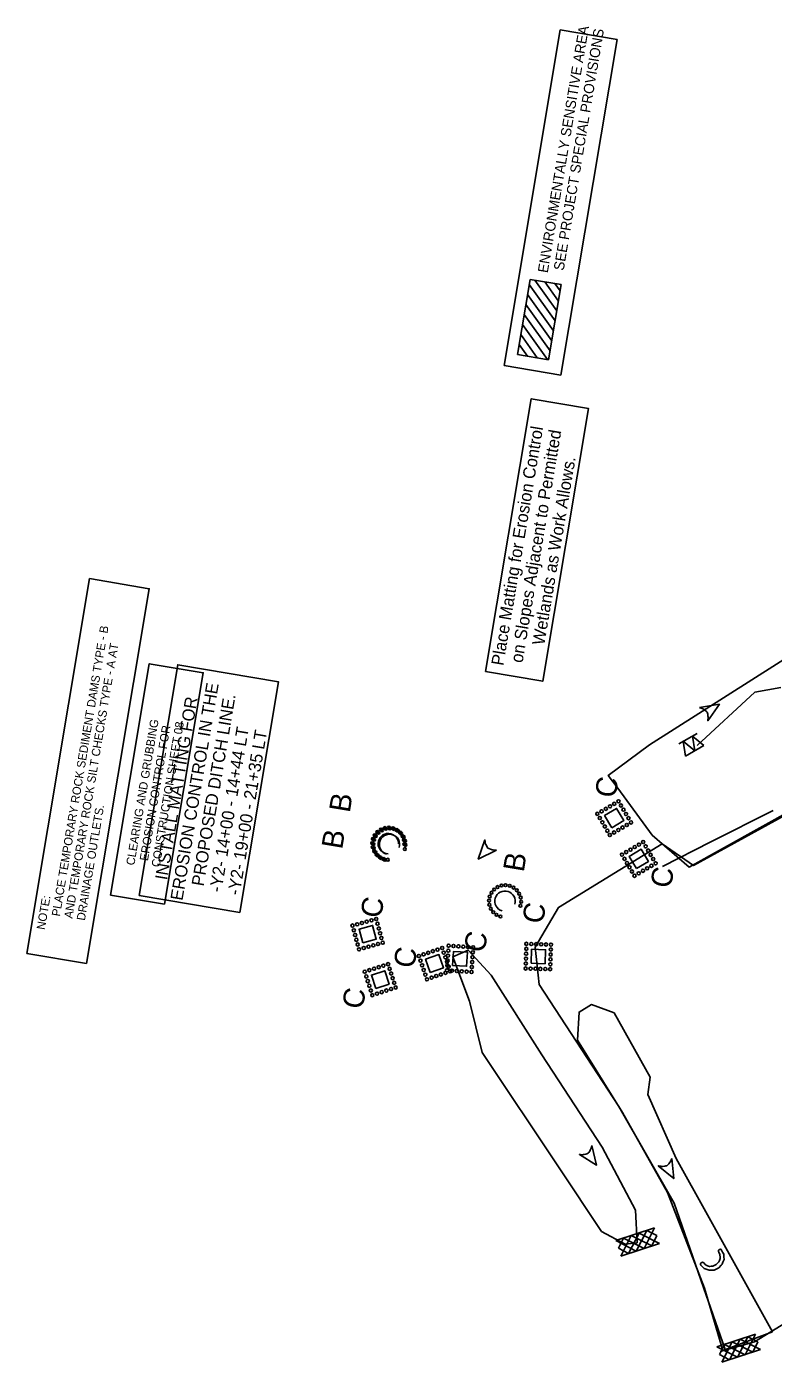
# Model space of a CAD drawing. Extents: x 2470000 to 2520000, y 340000 to 380000.
# Drawn here: x 2482102 to 2482633, y 367159 to 368109 of the extents above; entities that cross this region are included whole.
import ezdxf

# ---------------------------------------------------------------- set-up
doc = ezdxf.new("R2010")
doc.units = 0
for name, color, linetype in [('Bare Soil (Coastal) Drainage Area Border FG Drainage', 7, 'Continuous'), ('Construction Sheet Number Note CG CELL', 7, 'Continuous'), ('Environmentally Sensitive Area Note CG CELL', 7, 'Continuous'), ('Label B CG CELL', 7, 'Continuous'), ('Label B Final CELL', 7, 'Continuous'), ('Matting in Proposed Ditchline Note Final CELL', 7, 'Continuous'), ('Matting on Slope at Wetlands Note Final CELL', 7, 'Continuous'), ('Prop Guardrail', 7, 'Continuous'), ('Rock Pipe Inlet Sediment Trap Type B CG CELL', 7, 'Continuous'), ('Rock Pipe Inlet Sediment Trap Type B Final CELL', 7, 'Continuous'), ('Rock Silt Check Type A Both CELL', 7, 'Continuous'), ('Rock Silt Check Type B CG CELL', 7, 'Continuous'), ('Scratch_Level_5', 7, 'Continuous'), ('Sediment Dams and Silt Check Note CG CELL', 7, 'Continuous'), ('Special Sediment Control Fence Section Final CELL', 7, 'Continuous'), ('Temporary Silt Fence Final', 7, 'Continuous'), ('Wattle Both CELL', 7, 'Continuous')]:
    doc.layers.add(name, color=color, linetype=linetype)

# ---------------------------------------------------------------- blocks, each defined once
blk = doc.blocks.new('C3')
at = {"layer": 'Prop Guardrail'}
blk.add_text('C', height=0.3, dxfattribs=at).set_placement((-0.161, -0.136))
blk = doc.blocks.new('CGNT2')
at = {"layer": 'Sediment Dams and Silt Check Note CG CELL'}
blk.add_lwpolyline([(-2.704, 0.431), (2.704, 0.43125), (2.704, -0.43), (-2.704, -0.43)], close=True, dxfattribs=at)
for s, p in [('NOTE:', (-2.335, 0.231)), ('     PLACE TEMPORARY ROCK SEDIMENT DAMS TYPE - B', (-2.335, 0.05125)), ('     AND TEMPORARY ROCK SILT CHECKS TYPE - A AT', (-2.335, -0.129)), ('     DRAINAGE OUTLETS.', (-2.335, -0.309))]:
    blk.add_text(s, height=0.12, dxfattribs=at).set_placement(p)
blk = doc.blocks.new('B1')
at = {"layer": 'Label B CG CELL'}
blk.add_text('B', height=0.3, dxfattribs=at).set_placement((-0.106, -0.151))
blk = doc.blocks.new('B3')
at = {"layer": 'Label B Final CELL'}
blk.add_text('B', height=0.3, dxfattribs=at).set_placement((-0.106, -0.151))
blk = doc.blocks.new('MATSLOPEWET')
at = {"layer": 'Matting on Slope at Wetlands Note Final CELL'}
blk.add_lwpolyline([(-1.851, 0.435), (2.086, 0.435), (2.086, -0.39), (-1.851, -0.39)], close=True, dxfattribs=at)
for s, p in [('Place Matting for Erosion Control', (-1.733, 0.199)), ('on Slopes Adjacent to Permitted', (-1.649, -0.064)), ('Wetlands as Work Allows. ', (-1.349, -0.328))]:
    blk.add_text(s, height=0.17569, dxfattribs=at).set_placement(p)

msp = doc.modelspace()

# ---------------------------------------------------------------- linework, layer by layer
at = {"layer": 'Bare Soil (Coastal) Drainage Area Border FG Drainage'}
for points in [[(2482695.58, 367580.14), (2482733.84, 367608.85), (2482716.34, 367636.65), (2482690.63, 367690.71), (2482545.08, 367598.01), (2482515.7, 367576.31), (2482522.38, 367567.27), (2482547.02, 367533.91), (2482573.34, 367511.14), (2482699.03, 367581.01)], [(2482595.21, 367166.32), (2482619.75, 367173.34), (2482682.86, 367212.09), (2482758.96, 367340.68), (2482702.55, 367547.73), (2482665.92, 367561.27), (2482576.36, 367512.28), (2482554.09, 367527.55), (2482480.29, 367482.43), (2482463.55, 367454.21), (2482466.48, 367427.48), (2482523.08, 367340.84), (2482562.66, 367271.9), (2482583.45, 367212.07), (2482598.79, 367167.93)], [(2482536.25, 367243.82), (2482535.06, 367267.03), (2482511.35, 367311.91), (2482468.3, 367377.44), (2482432.22, 367434.11), (2482416.01, 367452.1), (2482404.98, 367447.31), (2482416.78, 367415.69), (2482425.94, 367379.17), (2482480.67, 367297.21), (2482510.95, 367251.86), (2482527.74, 367242.92)], [(2482597.34, 367167.09), (2482632.58, 367180.48), (2482586.27, 367263.61), (2482563.96, 367303.65), (2482543.72, 367349.35), (2482545.43, 367361.63), (2482519.8, 367407.5), (2482503.66, 367413.25), (2482494.87, 367407.92), (2482493.76, 367387.92), (2482525.87, 367336.43), (2482557.85, 367279.61), (2482584.15, 367211.48)]]:
    msp.add_lwpolyline(points, close=True, dxfattribs=at)
at = {"layer": 'Construction Sheet Number Note CG CELL'}
msp.add_lwpolyline([(2482161.23, 367491.21), (2482188.83, 367655.82), (2482227.3, 367649.37), (2482199.71, 367484.77)], close=True, dxfattribs=at)
at = {"layer": 'Environmentally Sensitive Area Note CG CELL'}
for p, q in [((2482441.48, 367867.98), (2482481.53, 368106.86)), ((2482481.53, 368106.86), (2482521.96, 368100.08)), ((2482521.96, 368100.08), (2482481.95, 367861.19)), ((2482451.02, 367875.81), (2482459.99, 367929.32)), ((2482477.83, 367899.68), (2482459.36, 367925.55)), ((2482459.99, 367929.32), (2482482.18, 367925.59)), ((2482479.02, 367906.8), (2482463.38, 367928.74)), ((2482480.22, 367913.9), (2482470.53, 367927.55)), ((2482482.18, 367925.59), (2482473.21, 367872.09)), ((2482481.41, 367921.03), (2482477.64, 367926.35)), ((2482476.64, 367892.57), (2482458.17, 367918.44)), ((2482475.45, 367885.45), (2482456.98, 367911.33)), ((2482472.3, 367872.25), (2482454.59, 367897.09)), ((2482474.25, 367878.34), (2482455.78, 367904.21)), ((2482465.15, 367873.44), (2482453.4, 367889.98)), ((2482458.04, 367874.64), (2482452.2, 367882.86)), ((2482481.95, 367861.19), (2482441.48, 367867.98)), ((2482473.21, 367872.09), (2482451.02, 367875.81))]:
    msp.add_line(p, q, dxfattribs=at)
at = {"layer": 'Matting in Proposed Ditchline Note Final CELL'}
msp.add_lwpolyline([(2482181.65, 367490.9), (2482209.16, 367655.03), (2482280.79, 367643.02), (2482253.29, 367478.89)], close=True, dxfattribs=at)
at = {"layer": 'Rock Pipe Inlet Sediment Trap Type B CG CELL'}
for centre in [(2482349.38, 367533.82), (2482351.27, 367536.13), (2482353.69, 367537.87), (2482356.48, 367538.92), (2482359.45, 367539.22), (2482362.39, 367538.73), (2482365.11, 367537.5), (2482367.42, 367535.61), (2482347.67, 367528.16), (2482347.96, 367525.19), (2482348.15, 367531.1), (2482369.16, 367533.19), (2482370.21, 367530.4), (2482370.5, 367527.43), (2482349.02, 367522.4), (2482350.76, 367519.98), (2482353.06, 367518.09), (2482355.78, 367516.86), (2482358.72, 367516.38), (2482436.81, 367496.92), (2482439.61, 367497.96), (2482442.57, 367498.25), (2482445.52, 367497.76), (2482448.23, 367496.52), (2482430.76, 367487.23), (2482431.25, 367490.17), (2482432.49, 367492.89), (2482434.38, 367495.19), (2482450.53, 367494.62), (2482452.26, 367492.19), (2482453.31, 367489.4), (2482453.59, 367486.43), (2482431.04, 367484.26), (2482432.09, 367481.47), (2482433.82, 367479.04), (2482436.12, 367477.14), (2482453.1, 367483.49), (2482438.84, 367475.91)]:
    msp.add_circle(centre, 1.01, dxfattribs=at)
for centre, start, end in [((2482359.09, 367527.8), 358.18137, 268.17255), ((2482442.18, 367486.83), 343.00443, 252.99561)]:
    msp.add_arc(centre, 7.26, start, end, dxfattribs=at)
at = {"layer": 'Rock Pipe Inlet Sediment Trap Type B Final CELL'}
for centre in [(2482352.05, 367535.51), (2482354.47, 367537.26), (2482357.25, 367538.32), (2482360.22, 367538.63), (2482363.16, 367538.15), (2482365.88, 367536.93), (2482368.2, 367535.05), (2482348.48, 367527.53), (2482348.78, 367524.56), (2482348.95, 367530.47), (2482350.17, 367533.19), (2482369.95, 367532.64), (2482370.84, 367523.94), (2482371.01, 367529.85), (2482371.32, 367526.88), (2482349.85, 367521.77), (2482351.59, 367519.36), (2482353.91, 367517.48), (2482356.63, 367516.26)]:
    msp.add_circle(centre, 1.01, dxfattribs=at)
msp.add_arc((2482359.9, 367527.21), 7.26, 343.3928, 253.38398, dxfattribs=at)
at = {"layer": 'Rock Silt Check Type A Both CELL'}
for p, q in [((2482521.05, 367245.33), (2482548.51, 367254.32)), ((2482537.54, 367250.72), (2482530.11, 367236.14)), ((2482543, 367252.53), (2482535.62, 367237.94)), ((2482552.11, 367243.34), (2482537.54, 367250.72)), ((2482548.51, 367254.32), (2482541.13, 367239.75)), ((2482550.31, 367248.86), (2482543, 367252.53)), ((2482535.62, 367237.94), (2482521.05, 367245.33)), ((2482526.48, 367247.05), (2482522.83, 367239.86)), ((2482530.11, 367236.14), (2482522.83, 367239.86)), ((2482532.02, 367248.92), (2482524.64, 367234.35)), ((2482524.64, 367234.35), (2482552.11, 367243.34)), ((2482541.13, 367239.75), (2482526.51, 367247.11)), ((2482546.6, 367241.54), (2482532.02, 367248.92)), ((2482550.31, 367248.86), (2482546.6, 367241.54)), ((2482592.98, 367169.73), (2482620.45, 367178.73)), ((2482603.96, 367173.33), (2482596.58, 367158.76)), ((2482609.47, 367175.13), (2482602.04, 367160.55)), ((2482618.53, 367165.95), (2482603.96, 367173.33)), ((2482614.93, 367176.93), (2482607.55, 367162.35)), ((2482624.04, 367167.75), (2482609.47, 367175.13)), ((2482620.45, 367178.73), (2482613.07, 367164.16)), ((2482622.25, 367173.27), (2482614.93, 367176.93)), ((2482622.25, 367173.27), (2482618.53, 367165.95)), ((2482607.55, 367162.35), (2482592.98, 367169.73)), ((2482598.42, 367171.46), (2482594.76, 367164.26)), ((2482602.04, 367160.55), (2482594.76, 367164.26)), ((2482596.58, 367158.76), (2482624.04, 367167.75)), ((2482613.07, 367164.16), (2482598.45, 367171.52))]:
    msp.add_line(p, q, dxfattribs=at)
at = {"layer": 'Rock Silt Check Type B CG CELL'}
for points in [[(2482580.6, 367624.55), (2482594.8, 367626.97), (2482586.46, 367615.24), (2482586.58, 367616.08), (2482586.71, 367617.1), (2482586.71, 367617.98), (2482586.66, 367618.6), (2482586.44, 367619.88), (2482586.24, 367620.66), (2482586.04, 367621.46), (2482585.43, 367622.05), (2482584.51, 367622.76), (2482583.9, 367623.19), (2482583.53, 367623.37), (2482583.08, 367623.63), (2482582.45, 367623.94), (2482581.86, 367624.15), (2482581.11, 367624.4)], [(2482436.04, 367523.2), (2482423.11, 367516.86), (2482427.78, 367530.47), (2482427.91, 367529.63), (2482428.07, 367528.62), (2482428.33, 367527.77), (2482428.55, 367527.19), (2482429.12, 367526.03), (2482429.53, 367525.34), (2482429.95, 367524.63), (2482430.7, 367524.23), (2482431.78, 367523.81), (2482432.49, 367523.58), (2482432.89, 367523.5), (2482433.41, 367523.39), (2482434.1, 367523.26), (2482434.72, 367523.23), (2482435.51, 367523.2)], [(2482503.96, 367313.08), (2482507.33, 367299.09), (2482495.06, 367306.61), (2482495.91, 367306.55), (2482496.93, 367306.48), (2482497.81, 367306.55), (2482498.42, 367306.64), (2482499.69, 367306.95), (2482500.45, 367307.19), (2482501.24, 367307.45), (2482501.78, 367308.1), (2482502.43, 367309.06), (2482502.82, 367309.7), (2482502.97, 367310.08), (2482503.2, 367310.55), (2482503.47, 367311.2), (2482503.64, 367311.8), (2482503.84, 367312.56)], [(2482560.88, 367303.79), (2482562.32, 367289.47), (2482551.19, 367298.58), (2482552.03, 367298.41), (2482553.03, 367298.21), (2482553.91, 367298.16), (2482554.53, 367298.16), (2482555.82, 367298.29), (2482556.61, 367298.43), (2482557.42, 367298.58), (2482558.06, 367299.15), (2482558.82, 367300.02), (2482559.29, 367300.6), (2482559.5, 367300.95), (2482559.79, 367301.39), (2482560.15, 367301.99), (2482560.39, 367302.56), (2482560.7, 367303.29)]]:
    msp.add_lwpolyline(points, close=True, dxfattribs=at)
at = {"layer": 'Scratch_Level_5'}
for points in [[(2482518.13, 367539.1), (2482513.02, 367547.7), (2482521.62, 367552.81), (2482526.71, 367544.21)], [(2482535.67, 367510.08), (2482530.58, 367518.69), (2482539.19, 367523.78), (2482544.26, 367515.16)], [(2482340.85, 367457.27), (2482338.19, 367466.91), (2482347.83, 367469.56), (2482350.47, 367459.92)], [(2482404.85, 367441.18), (2482405.51, 367451.16), (2482415.48, 367450.5), (2482414.82, 367440.52)], [(2482460.72, 367442.63), (2482461.03, 367452.62), (2482471.02, 367452.32), (2482470.71, 367442.32)], [(2482388.89, 367436.08), (2482385.62, 367445.53), (2482395.08, 367448.8), (2482398.33, 367439.34)], [(2482350.1, 367424.74), (2482347.01, 367434.25), (2482356.52, 367437.34), (2482359.6, 367427.83)]]:
    msp.add_lwpolyline(points, close=True, dxfattribs=at)
for centre in [(2482513.89, 367552.57), (2482516.9, 367554.36), (2482519.91, 367556.14), (2482522.91, 367557.93), (2482524.7, 367554.92), (2482507.87, 367548.99), (2482509.66, 367545.98), (2482510.88, 367550.78), (2482511.44, 367542.98), (2482526.49, 367551.91), (2482528.28, 367548.91), (2482530.07, 367545.9), (2482531.85, 367542.89), (2482513.23, 367539.97), (2482515.02, 367536.96), (2482516.81, 367533.95), (2482519.82, 367535.74), (2482522.83, 367537.52), (2482525.84, 367539.31), (2482528.84, 367541.1), (2482534.47, 367525.34), (2482537.48, 367527.12), (2482540.49, 367528.9), (2482542.28, 367525.88), (2482525.43, 367519.99), (2482527.21, 367516.98), (2482528.44, 367521.77), (2482531.46, 367523.55), (2482544.06, 367522.87), (2482545.84, 367519.86), (2482547.62, 367516.85), (2482528.99, 367513.97), (2482530.77, 367510.95), (2482532.55, 367507.94), (2482534.34, 367504.93), (2482537.35, 367506.71), (2482540.36, 367508.49), (2482543.37, 367510.27), (2482546.39, 367512.05), (2482549.4, 367513.83), (2482333.56, 367469.51), (2482336.93, 367470.44), (2482340.31, 367471.37), (2482343.68, 367472.3), (2482347.06, 367473.23), (2482350.43, 367474.16), (2482351.36, 367470.79), (2482352.29, 367467.41), (2482334.49, 367466.14), (2482335.42, 367462.76), (2482336.35, 367459.39), (2482353.22, 367464.04), (2482354.15, 367460.67), (2482355.08, 367457.29), (2482337.28, 367456.02), (2482338.21, 367452.64), (2482341.59, 367453.57), (2482344.96, 367454.5), (2482348.33, 367455.43), (2482351.71, 367456.36), (2482380.84, 367447.84), (2482384.15, 367448.98), (2482387.46, 367450.12), (2482390.77, 367451.27), (2482394.07, 367452.41), (2482397.38, 367453.55), (2482398.52, 367450.24), (2482401.53, 367448.15), (2482401.76, 367451.64), (2482401.99, 367455.14), (2482405.48, 367454.91), (2482408.98, 367454.68), (2482412.47, 367454.45), (2482415.96, 367454.22), (2482419.23, 367450.5), (2482419.45, 367453.99), (2482457.16, 367449.48), (2482457.27, 367452.98), (2482457.38, 367456.48), (2482460.87, 367456.37), (2482464.37, 367456.26), (2482467.87, 367456.16), (2482471.37, 367456.05), (2482474.65, 367448.95), (2482474.76, 367452.44), (2482474.87, 367455.94), (2482348.93, 367438.81), (2482352.26, 367439.89), (2482355.58, 367440.97), (2482358.91, 367442.05), (2482359.99, 367438.72), (2482381.98, 367444.53), (2482383.12, 367441.22), (2482399.67, 367446.93), (2482400.81, 367443.63), (2482401.07, 367441.17), (2482401.3, 367444.66), (2482401.95, 367440.32), (2482418.54, 367440.02), (2482418.77, 367443.51), (2482419, 367447), (2482456.84, 367438.99), (2482456.95, 367442.48), (2482457.06, 367445.98), (2482460.34, 367438.88), (2482463.84, 367438.77), (2482467.34, 367438.67), (2482470.84, 367438.56), (2482474.33, 367438.45), (2482474.44, 367441.95), (2482474.55, 367445.45), (2482342.27, 367436.64), (2482343.35, 367433.31), (2482344.43, 367429.99), (2482345.6, 367437.73), (2482361.08, 367435.4), (2482362.16, 367432.07), (2482363.24, 367428.74), (2482384.27, 367437.91), (2482385.41, 367434.61), (2482386.55, 367431.3), (2482389.86, 367432.44), (2482393.17, 367433.58), (2482396.48, 367434.72), (2482399.79, 367435.87), (2482400.84, 367437.67), (2482403.09, 367437.01), (2482404.34, 367437.44), (2482407.83, 367437.21), (2482411.32, 367436.99), (2482414.81, 367436.76), (2482418.31, 367436.53), (2482345.52, 367426.66), (2482346.6, 367423.33), (2482347.68, 367420), (2482351.01, 367421.08), (2482354.34, 367422.16), (2482357.67, 367423.25), (2482360.99, 367424.33), (2482364.32, 367425.41)]:
    msp.add_circle(centre, 1.12, dxfattribs=at)
at = {"layer": 'Special Sediment Control Fence Section Final CELL'}
for p, q in [((2482565.81, 367598.86), (2482578.88, 367606.22)), ((2482570.72, 367590.15), (2482583.79, 367597.51))]:
    msp.add_line(p, q, dxfattribs=at)
for points in [[(2482577.25, 367593.83), (2482575.61, 367604.38), (2482583.79, 367597.51)], [(2482570.72, 367590.15), (2482569.08, 367600.7), (2482577.25, 367593.83)]]:
    msp.add_lwpolyline(points, dxfattribs=at)
at = {"layer": 'Temporary Silt Fence Final'}
for p, q in [((2482620.05, 367635.68), (2482638.63, 367638.89)), ((2482578.86, 367597.68), (2482620.05, 367635.68)), ((2482588.8, 367529.03), (2482633.13, 367551.43)), ((2482554.18, 367511.48), (2482588.8, 367529.03))]:
    msp.add_line(p, q, dxfattribs=at)
at = {"layer": 'Wattle Both CELL'}
for p, q in [((2482595.06, 367235.41), (2482594.26, 367237.09)), ((2482594.36, 367230.15), (2482594.81, 367231.26)), ((2482594.81, 367231.26), (2482595.35, 367232.6)), ((2482595.06, 367235.41), (2482595.2, 367235.11)), ((2482595.29, 367233.63), (2482595.2, 367235.11)), ((2482595.35, 367232.6), (2482595.29, 367233.63)), ((2482583.59, 367229.49), (2482584.71, 367228.41)), ((2482584.71, 367228.41), (2482585.28, 367227.87)), ((2482585.28, 367227.87), (2482586.32, 367227.48)), ((2482586.32, 367227.48), (2482587.68, 367226.98)), ((2482587.91, 367226.99), (2482587.68, 367226.98)), ((2482587.91, 367226.99), (2482589.02, 367227.08)), ((2482590.21, 367227.16), (2482589.02, 367227.08)), ((2482590.21, 367227.16), (2482592.57, 367228.32)), ((2482592.58, 367228.33), (2482592.57, 367228.32)), ((2482592.58, 367228.33), (2482594.36, 367230.15))]:
    msp.add_line(p, q, dxfattribs=at)
msp.add_lwpolyline([(2482596.36, 367238.62), (2482597.05, 367237.22), (2482597.85, 367235.59), (2482597.91, 367234.76), (2482597.97, 367233.75), (2482598.08, 367231.96), (2482598.06, 367231.92), (2482597.91, 367231.51), (2482597.88, 367231.43), (2482597.54, 367230.54), (2482597.31, 367229.92), (2482596.79, 367228.55), (2482596.08, 367227.79), (2482594.33, 367225.93), (2482594.32, 367225.92), (2482591.94, 367224.79), (2482591.01, 367224.35), (2482589.88, 367224.3), (2482589.64, 367224.29), (2482588.68, 367224.25), (2482587.95, 367224.21), (2482587.78, 367224.21), (2482587.41, 367224.19), (2482587.41, 367224.19), (2482586, 367224.73), (2482584.74, 367225.22), (2482583.99, 367225.51), (2482582.7, 367226.71), (2482581.57, 367227.76)], dxfattribs=at)
for centre, radius, start in [((2482595.31, 367237.85), 1.3, 36.11546), ((2482582.65, 367228.55), 1.33, 45.00282)]:
    msp.add_arc(centre, radius, start, 216.11546, dxfattribs=at)

# ---------------------------------------------------------------- block references
at = {"layer": 'Label B CG CELL', "xscale": 49.99999999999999, "yscale": 50.00000000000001, "rotation": 80.48585657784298}
for p in [(2482324.99, 367555.77), (2482448.89, 367513.51)]:
    msp.add_blockref('B1', p, dxfattribs=at)
at = {"layer": 'Label B Final CELL', "xscale": 49.99999999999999, "yscale": 50.00000000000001, "rotation": 80.48585657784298}
msp.add_blockref('B3', (2482319.6, 367529.75), dxfattribs=at)
at = {"layer": 'Matting on Slope at Wetlands Note Final CELL', "xscale": 50, "yscale": 50, "rotation": 80.4822762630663}
msp.add_blockref('MATSLOPEWET', (2482465.05, 367737.85), dxfattribs=at)
at = {"layer": 'Scratch_Level_5', "xscale": 50, "yscale": 50, "rotation": 80.48585657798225}
for p in [(2482515.32, 367568.79), (2482554.85, 367504.61), (2482348.45, 367483.26), (2482463.69, 367479.23), (2482422.15, 367458.79), (2482371.99, 367447.63), (2482335.44, 367418.56)]:
    msp.add_blockref('C3', p, dxfattribs=at)
at = {"layer": 'Sediment Dams and Silt Check Note CG CELL', "xscale": 50.000000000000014, "yscale": 50.000000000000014, "rotation": 80.4715380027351}
msp.add_blockref('CGNT2', (2482145.25, 367579.44), dxfattribs=at)

# ---------------------------------------------------------------- texts
at = {"layer": 'Construction Sheet Number Note CG CELL'}
for s, p in [('CLEARING AND GRUBBING', (2482178.22, 367512.02)), ('EROSION CONTROL FOR', (2482187.88, 367515.19)), ('CONSTRUCTION SHEET 08', (2482196.25, 367510.71))]:
    msp.add_text(s, height=6, rotation=80.48586, dxfattribs=at).set_placement(p)
at = {"layer": 'Environmentally Sensitive Area Note CG CELL'}
for s, p in [('ENVIRONMENTALLY SENSITIVE AREA', (2482472.55, 367933.51)), ('SEE PROJECT SPECIAL PROVISIONS', (2482483.87, 367935.17))]:
    msp.add_text(s, height=7.26, rotation=80.48788, dxfattribs=at).set_placement(p)
at = {"layer": 'Matting in Proposed Ditchline Note Final CELL'}
for s, p in [('EROSION CONTROL IN THE', (2482212.49, 367486.91)), ('INSTALL MATTING FOR ', (2482201.57, 367501.49)), ('PROPOSED DITCH LINE.', (2482227.56, 367497.13)), ('-Y2- 14+00 - 14+44 LT', (2482240.2, 367492.82)), ('-Y2- 19+00 - 21+35 LT', (2482253.2, 367490.64))]:
    msp.add_text(s, height=8.7846, rotation=80.48586, dxfattribs=at).set_placement(p)

doc.saveas('drawing.dxf')
